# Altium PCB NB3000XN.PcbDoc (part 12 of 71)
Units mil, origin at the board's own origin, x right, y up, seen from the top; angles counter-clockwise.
Board outline 9527.56 x 6929.77 mil, 6 copper layers (Top Layer, GND+SHIELD, MidLayer1, MidLayer2, P2 - 3V3+5V0, Bottom Layer), stack 62.375 mil thick; 832 components, 1027 nets, 4655 pads, 4981 vias.
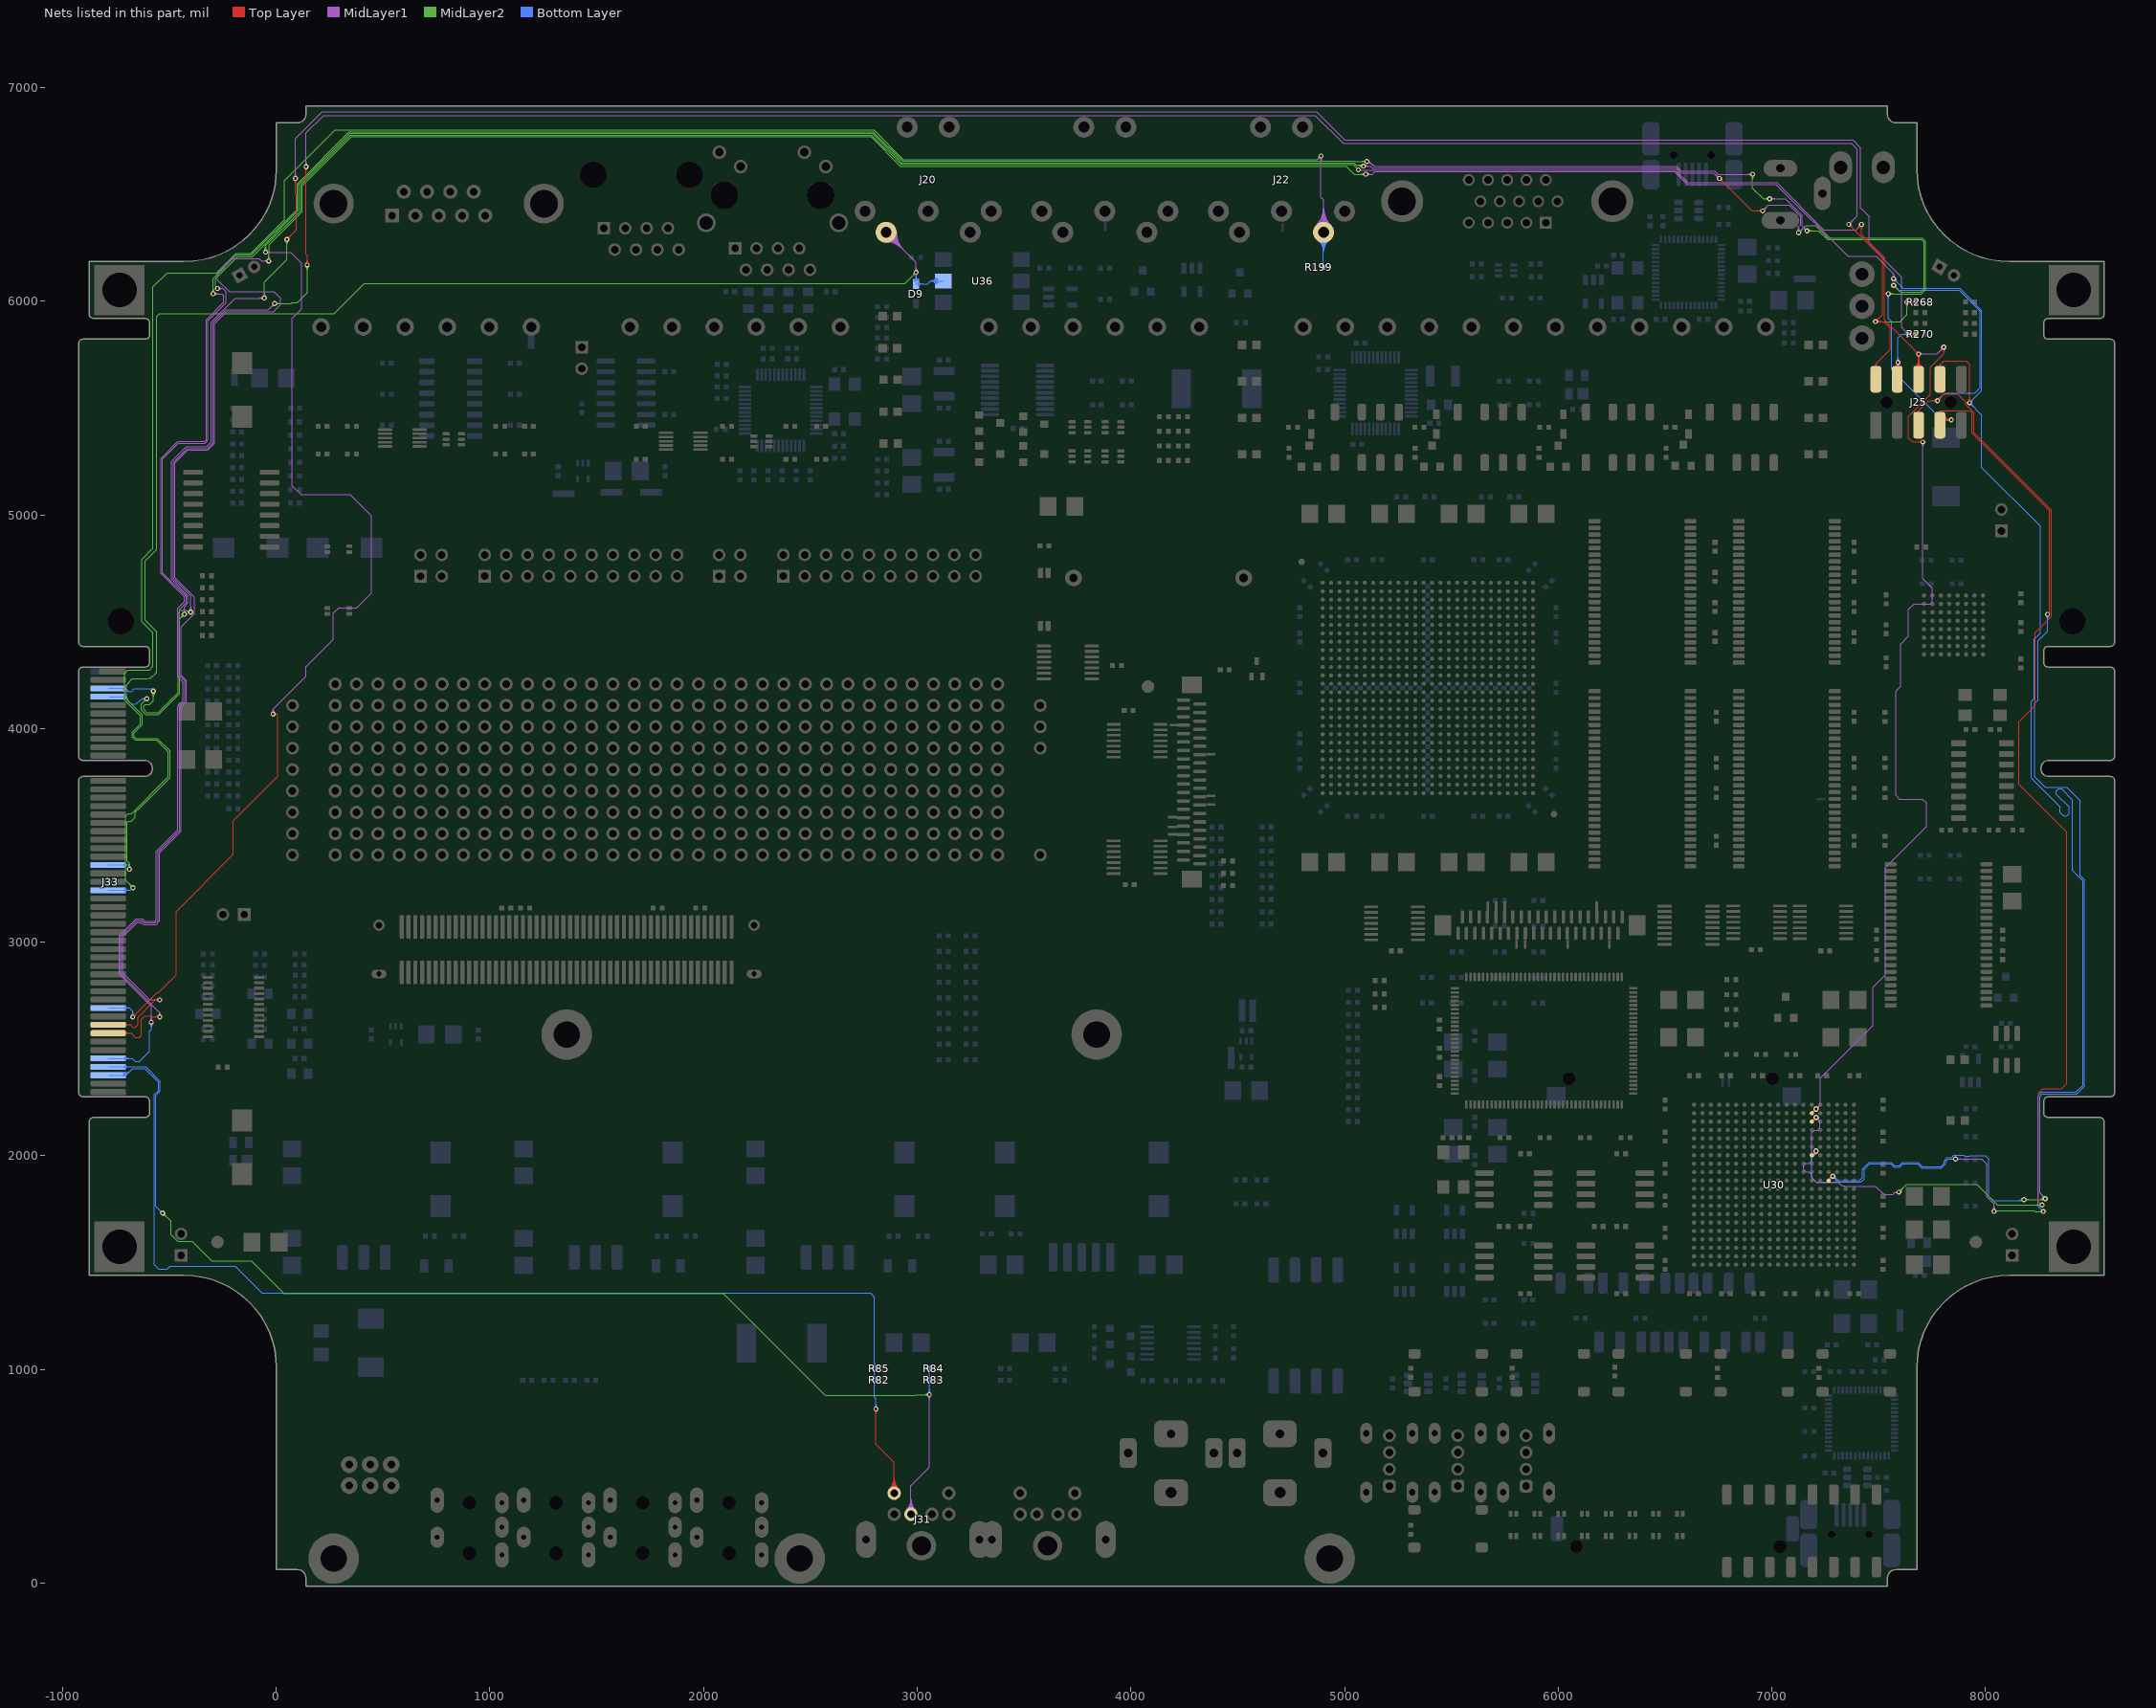
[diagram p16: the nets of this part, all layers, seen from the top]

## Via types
v1: diameter 23, hole 11.81, Top Layer to Bottom Layer, 3672 vias
v2: diameter 26, hole 11.81, Top Layer to Bottom Layer, 461 vias
v3: diameter 19, hole 11.81, Top Layer to Bottom Layer, tented both sides, 396 vias
v4: diameter 23.62, hole 11.81, Top Layer to Bottom Layer, 288 vias
v5: diameter 20, hole 11.81, Top Layer to Bottom Layer, 91 vias
v6: diameter 23, hole 11.81, Top Layer to Bottom Layer, tented both sides, 50 vias
v7: diameter 31, hole 11.81, Top Layer to Bottom Layer, 15 vias
v8: diameter 27.56, hole 11.81, Top Layer to Bottom Layer, tented both sides, 4 vias
v9: diameter 29, hole 11.81, Top Layer to Bottom Layer, 3 vias
v10: diameter 21, hole 11.81, Top Layer to Bottom Layer, 1 vias

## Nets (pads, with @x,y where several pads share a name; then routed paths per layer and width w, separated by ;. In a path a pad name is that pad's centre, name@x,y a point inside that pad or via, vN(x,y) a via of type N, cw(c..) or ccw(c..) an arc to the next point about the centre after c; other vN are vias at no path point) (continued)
ATE.HOST_JTAG.HARD.TDO: J25.2 J33.B3 R268.1 | length 13855.9
  Top Layer w4: v4@133.06,6623.06 cw(c116.31,6606.31) 140,6606.31 cw(c163.69,6606.31) v4@146.94,6623.06 ; v4@135.89,6625.89 cw(c125.97,6615.97) 140,6615.97 cw(c154.03,6615.97) v4@144.11,6625.89 ; v4@138.06,6176.94 ccw(c121.31,6193.69) 145,6193.69 ccw(c168.69,6193.69) v4@151.94,6176.94 ; v4(140,6630) 140,6220 145,6215 v4(145,6170) ; v4@140.89,6174.11 ccw(c130.97,6184.03) 145,6184.03 ccw(c159.03,6184.03) v4@149.11,6174.11 ; v4@7360,6350.19 cw(c7360,6326.5) 7376.75,6343.25 cw(c7393.5,6360) v4@7369.81,6360 ; v4@7360,6354.19 cw(c7360,6340.16) 7369.92,6350.08 cw(c7379.84,6360) v4@7365.81,6360 ; v4(7360,6360) 7518.05,6201.95 7518.05,5938.05 v4(7485,5905) 7524.05,5905 7555,5874.05 7555,5775 7486.99,5706.99 ; J25.2@7478.3,5694.04 ccw(c7473.01,5706.99) 7486.99,5706.99 ; J25.2@7479.81,5690.34 ccw(c7475.44,5701.04) 7486.99,5701.04 ccw(c7498.55,5701.04) J25.2@7494.18,5690.34 ; J25.2@7481.58,5695.1 ccw(c7479.91,5701.99) 7486.99,5701.99 ; J25.2@7484.89,5574.85 cw(c7484.68,5572.54) 7486.99,5572.54 ; v4@7485,5910.81 ccw(c7485,5924.84) 7494.92,5914.92 ccw(c7504.84,5905) v4@7490.81,5905 ; v4@7485,5914.81 ccw(c7485,5938.5) 7501.75,5921.75 ccw(c7518.5,5905) v4@7494.81,5905 ; J25.2@7489.1,5574.85 ccw(c7489.31,5572.54) 7486.99,5572.54 ; v4@7489.11,5900.89 cw(c7499.03,5890.97) 7499.03,5905 cw(c7499.03,5919.03) v4@7489.11,5909.11 ; v4@7491.94,5898.06 cw(c7508.69,5881.31) 7508.69,5905 cw(c7508.69,5928.69) v4@7491.94,5911.94 ; J25.2@7492.41,5695.1 cw(c7494.08,5701.99) 7486.99,5701.99 ; J25.2@7495.69,5694.04 cw(c7500.98,5706.99) 7486.99,5706.99 ; v4(7632,5997) R268.1@7673.82,5997 ; v4@7636.11,5992.89 cw(c7646.03,5982.97) 7646.03,5997 cw(c7646.03,6011.03) v4@7636.11,6001.11 ; v4@7638.94,5990.06 cw(c7655.69,5973.31) 7655.69,5997 cw(c7655.69,6020.69) v4@7638.94,6003.94 ; R268.1@7667.23,5990.41 ccw(c7651.32,5974.5) 7651.32,5997 ccw(c7651.32,6019.5) R268.1@7667.23,6003.59 ; R268.1@7670.06,5993.24 ccw(c7660.98,5984.16) 7660.98,5997 ccw(c7660.98,6009.84) R268.1@7670.06,6000.76 ; 7486.99,5572.54 J25.2@7486.99,5635.25 ; J25.2@7486.99,5635.25 J25.2@7486.99,5635.59 ; J25.2@7486.99,5635.25 J25.2@7486.99,5635.59 ; J25.2@7486.99,5635.59 7486.99,5706.99 ; J25.2@7486.99,5635.59 7486.99,5701.99
  MidLayer1 w4: v4@-406.94,4551.94 ccw(c-423.69,4568.69) -400,4568.69 ccw(c-376.31,4568.69) v4@-393.06,4551.94 ; v4@-404.11,4549.11 ccw(c-414.03,4559.03) -400,4559.03 ccw(c-385.97,4559.03) v4@-395.89,4549.11 ; v4(-400,4545) -400,4620 -407.83,4627.84 -482,4702 -482,5246.69 -417.12,5311.56 -322.46,5311.56 -295.52,5338.51 -295.52,5899.23 -234.74,5960 -36.47,5960 v4(-7.38,5989.09) ; v4@-17.19,5989.09 cw(c-40.87,5989.09) -24.13,5972.34 cw(c-7.38,5955.59) v4@-7.38,5979.28 ; v4@-13.19,5989.09 cw(c-27.22,5989.09) -17.3,5979.17 cw(c-7.38,5969.25) v4@-7.38,5983.28 ; v4@133.06,6636.94 ccw(c116.31,6653.69) 140,6653.69 ccw(c163.69,6653.69) v4@146.94,6636.94 ; v4@135.89,6634.11 ccw(c125.97,6644.03) 140,6644.03 ccw(c154.03,6644.03) v4@144.11,6634.11 ; v4(140,6630) 140,6788.69 221.59,6870.28 4862.1,6870.28 4993.37,6739 7372.06,6739 7400,6711.06 7400,6400 v4(7360,6360) ; v4@7360,6365.81 ccw(c7360,6379.84) 7369.92,6369.92 ccw(c7379.84,6360) v4@7365.81,6360 ; v4@7360,6369.81 ccw(c7360,6393.5) 7376.75,6376.75 ccw(c7393.5,6360) v4@7369.81,6360
  MidLayer2 w4: v4@-581.94,4168.06 cw(c-598.69,4151.31) -575,4151.31 cw(c-551.31,4151.31) v4@-568.06,4168.06 ; v4@-579.11,4170.89 cw(c-589.03,4160.97) -575,4160.97 cw(c-560.97,4160.97) v4@-570.89,4170.89 ; v4(-575,4175) -575,4131.31 -593.81,4112.5 -612.5,4112.5 -620,4105 -620,4090 -605.61,4075.61 -551.61,4075.61 -458.98,4168.24 -458.98,4541.21 -447.19,4553 -420,4553 -412,4545 v4(-400,4545) ; v4(-7.38,5989.09) 70.59,5989.09 75,5993.5 98.5,5993.5 145,6040 v4(145,6170) ; v4@-3.27,5984.98 cw(c6.65,5975.06) 6.65,5989.09 cw(c6.65,6003.12) v4@-3.27,5993.2 ; v4@-0.44,5982.15 cw(c16.31,5965.4) 16.31,5989.09 cw(c16.31,6012.77) v4@-0.44,5996.02 ; v4@138.06,6163.06 cw(c121.31,6146.31) 145,6146.31 cw(c168.69,6146.31) v4@151.94,6163.06 ; v4@140.89,6165.89 cw(c130.97,6155.97) 145,6155.97 cw(c159.03,6155.97) v4@149.11,6165.89 ; v4(7485,5905) 7600,5905 7632,5937 v4(7632,5997) ; v4@7489.11,5900.89 cw(c7499.03,5890.97) 7499.03,5905 cw(c7499.03,5919.03) v4@7489.11,5909.11 ; v4@7491.94,5898.06 cw(c7508.69,5881.31) 7508.69,5905 cw(c7508.69,5928.69) v4@7491.94,5911.94 ; v4@7625.06,5990.06 cw(c7608.31,5973.31) 7632,5973.31 cw(c7655.69,5973.31) v4@7638.94,5990.06 ; v4@7627.89,5992.89 cw(c7617.97,5982.97) 7632,5982.97 cw(c7646.03,5982.97) v4@7636.11,5992.89
  Bottom Layer w4: J33.B3@-785.98,4188.29 -705.14,4188.29 -691.06,4174.21 -676.56,4174.21 -664.89,4185.87 -580.87,4185.87 v4@-575,4180 ; J33.B3@-717.13,4188.51 cw(c-713.23,4170.99) -700.53,4183.68 ; J33.B3@-716.26,4184.61 cw(c-711.35,4162.57) -695.39,4178.53 ; J33.B3@-715.39,4180.7 cw(c-709.47,4154.15) -690.24,4173.39
ATE.HOST_JTAG.HARD.TMS: J25.4 J33.B4 R270.1 | length 13306.8
  Top Layer w4: v4(50,6290) 95,6335 95,6500 90,6505 v4(90,6575) ; v4@50,6295.81 ccw(c50,6309.84) 59.92,6299.92 ccw(c69.84,6290) v4@55.81,6290 ; v4@50,6299.81 ccw(c50,6323.5) 66.75,6306.75 ccw(c83.5,6290) v4@59.81,6290 ; v4@83.06,6568.06 cw(c66.31,6551.31) 90,6551.31 cw(c113.69,6551.31) v4@96.94,6568.06 ; v4@85.89,6570.89 cw(c75.97,6560.97) 90,6560.97 cw(c104.03,6560.97) v4@94.11,6570.89 ; J25.4@7577.2,5693.56 ccw(c7567.56,5714.04) v1(7590.19,5714.04) ; J25.4@7578.9,5689.94 ccw(c7570.52,5707.74) v1@7590.19,5707.74 ; J25.4@7580.6,5686.32 ccw(c7573.49,5701.43) 7590.19,5701.43 ; v1@7583.47,5707.32 cw(c7567.26,5691.11) 7590.19,5691.11 cw(c7613.13,5691.11) v1@7596.91,5707.32 ; J25.4@7585,5630 J25.4@7590.19,5635.19 ; v1@7586.3,5710.15 cw(c7576.91,5700.76) 7590.19,5700.76 cw(c7603.47,5700.76) v1@7594.08,5710.15 ; J25.4@7590.19,5635.25 v1(7590.19,5714.04) ; v1@7590.19,5705.7 ccw(c7613.44,5705.7) J25.4@7598.89,5687.57 ; J25.4@7601.39,5690.69 cw(c7620.13,5714.04) v1(7590.19,5714.04) ; v4(7640,5845) 7672.82,5845 R270.1@7673.82,5846 ; v4@7644.11,5840.89 cw(c7654.03,5830.97) 7654.03,5845 cw(c7654.03,5859.03) v4@7644.11,5849.11 ; v4@7646.94,5838.06 cw(c7663.69,5821.31) 7663.69,5845 cw(c7663.69,5868.69) v4@7646.94,5851.94 ; v4@7650.09,5845 ccw(c7650.09,5869.23) R270.1@7667.23,5852.1 ; 7652.55,5845 cw(c7652.55,5824.24) R270.1@7667.23,5838.92 ; 7659.75,5845 ccw(c7659.75,5859.57) R270.1@7670.06,5849.27 ; 7662.2,5845 cw(c7662.2,5833.89) R270.1@7670.06,5841.75
  MidLayer1 w4: v4@-436.94,4541.94 ccw(c-453.69,4558.69) -430,4558.69 ccw(c-406.31,4558.69) v4@-423.06,4541.94 ; v4@-434.11,4539.11 ccw(c-444.03,4549.03) -430,4549.03 ccw(c-415.97,4549.03) v4@-425.89,4539.11 ; v4(-430,4535) -430,4570.19 -413.5,4586.69 -413.5,4622.19 -490,4698.69 -490,5250 -420.44,5319.56 -325.78,5319.56 -303.52,5341.82 -303.52,5902.54 -191.06,6015 v4(-55,6015) ; v4@-61.94,6008.06 ccw(c-78.69,5991.31) -78.69,6015 ccw(c-78.69,6038.69) v4@-61.94,6021.94 ; v4@-59.11,6010.89 ccw(c-69.03,6000.97) -69.03,6015 ccw(c-69.03,6029.03) v4@-59.11,6019.11 ; v4@83.06,6581.94 ccw(c66.31,6598.69) 90,6598.69 ccw(c113.69,6598.69) v4@96.94,6581.94 ; v4@85.89,6579.11 ccw(c75.97,6589.03) 90,6589.03 ccw(c104.03,6589.03) v4@94.11,6579.11 ; v4(90,6575) 90,6761.31 214.96,6886.28 4868.72,6886.28 5000,6755 7378.69,6755 7416,6717.69 7416,6436.31 7454.85,6397.46 7454.85,6266.46 7590.26,6131.06 7608,6113.31 7608,5947 7608,5877 v4(7640,5845) ; v4@7630.19,5845 ccw(c7606.5,5845) 7623.25,5861.75 ccw(c7640,5878.5) v4@7640,5854.81 ; v4@7634.19,5845 ccw(c7620.16,5845) 7630.08,5854.92 ccw(c7640,5864.84) v4@7640,5850.81
  MidLayer2 w4: v4@-614.81,4140 cw(c-638.5,4140) -621.75,4123.25 cw(c-605,4106.5) v4@-605,4130.19 ; v4@-610.81,4140 cw(c-624.84,4140) -614.92,4130.08 cw(c-605,4120.16) v4@-605,4134.19 ; v4(-605,4140) -630,4115 -630,4085 -610,4065 -550.9,4065 -450.98,4164.93 -450.98,4514.02 v4(-430,4535) ; v4@-439.81,4535 cw(c-463.5,4535) -446.75,4518.25 cw(c-430,4501.5) v4@-430,4525.19 ; v4@-435.81,4535 cw(c-449.84,4535) -439.92,4525.08 cw(c-430,4515.16) v4@-430,4529.19 ; v4@-61.94,6021.94 ccw(c-78.69,6038.69) -55,6038.69 ccw(c-31.31,6038.69) v4@-48.06,6021.94 ; v4@-59.11,6019.11 ccw(c-69.03,6029.03) -55,6029.03 ccw(c-40.97,6029.03) v4@-50.89,6019.11 ; v4(-55,6015) -55,6090 50,6195 v4(50,6290) ; v4@43.06,6283.06 cw(c26.31,6266.31) 50,6266.31 cw(c73.69,6266.31) v4@56.94,6283.06 ; v4@45.89,6285.89 cw(c35.97,6275.97) 50,6275.97 cw(c64.03,6275.97) v4@54.11,6285.89
  Bottom Layer w4: J33.B4@-780,4148.92 -703.95,4148.92 -695,4139.98 -695,4131 -679,4115 -655,4115 -633.87,4136.13 -629.86,4136.13 -625.99,4140 ; J33.B4@-717.17,4149.13 cw(c-711.42,4135.58) -701.01,4145.99 ; J33.B4@-715.61,4145.45 cw(c-708.92,4129.69) -696.82,4141.79 ; v4@-612.53,4133.71 ccw(c-625.99,4122.46) -625.99,4140 ; v4@-612.53,4146.29 cw(c-625.99,4157.54) -625.99,4140 ; v4@-609.46,4136.27 ccw(c-617.43,4129.61) -617.43,4140 ccw(c-617.43,4150.39) v4@-609.46,4143.73 ; v4(-605,4140) -625.99,4140 ; v1@7583.47,5720.76 ccw(c7567.26,5736.98) 7590.19,5736.98 ccw(c7613.13,5736.98) v1@7596.91,5720.76 ; v1@7586.3,5717.93 ccw(c7576.91,5727.32) 7590.19,5727.32 ccw(c7603.47,5727.32) v1@7594.08,5717.93 ; v1(7590.19,5714.04) 7590.19,5827.37 7607.82,5845 v4(7640,5845) ; v4@7633.06,5838.06 ccw(c7616.31,5821.31) 7616.31,5845 ccw(c7616.31,5868.69) v4@7633.06,5851.94 ; v4@7635.89,5840.89 ccw(c7625.97,5830.97) 7625.97,5845 ccw(c7625.97,5859.03) v4@7635.89,5849.11
ATE.HOST_JTAG.SOFT.TCK: J25.7 J33.A42 U30.D10 | length 21667.9
  Top Layer w4: J33.A42@-785.98,2574.12 -679.12,2574.12 -660,2555 -640,2555 -630,2565 -630,2640 -615,2655 -585,2655 -580,2650 v4(-545,2650) ; J33.A42@-711.58,2568.62 cw(c-698.3,2555.34) -698.3,2574.12 cw(c-698.3,2592.9) J33.A42@-711.58,2579.62 ; J33.A42@-708.76,2565.79 cw(c-688.65,2545.68) -688.65,2574.12 cw(c-688.65,2602.56) J33.A42@-708.76,2582.45 ; v4@-551.94,2643.06 ccw(c-568.69,2626.31) -568.69,2650 ccw(c-568.69,2673.69) v4@-551.94,2656.94 ; v4@-549.11,2645.89 ccw(c-559.03,2635.97) -559.03,2650 ccw(c-559.03,2664.03) v4@-549.11,2654.11 ; v4@6755,6565.19 cw(c6755,6541.5) 6771.75,6558.25 cw(c6788.5,6575) v4@6764.81,6575 ; v4@6755,6569.19 cw(c6755,6555.16) 6764.92,6565.08 cw(c6774.84,6575) v4@6760.81,6575 ; v4(6755,6575) 6907,6423 v4(6957,6423) ; v4@6950.06,6416.06 ccw(c6933.31,6399.31) 6933.31,6423 ccw(c6933.31,6446.69) v4@6950.06,6429.94 ; v4@6952.89,6418.89 ccw(c6942.97,6408.97) 6942.97,6423 ccw(c6942.97,6437.03) v4@6952.89,6427.11 ; J25.7@7781.58,5480.1 ccw(c7779.91,5486.99) 7786.99,5486.99 ; J25.7@7789.78,5458.88 ccw(c7810.35,5467.19) J25.7@7810.35,5445 ; J25.7@7792.41,5480.1 cw(c7794.08,5486.99) 7786.99,5486.99 ; J25.7@7793.48,5460.37 ccw(c7816.28,5469.58) 7816.28,5445 ; J25.7@7797.19,5461.87 ccw(c7822.21,5471.98) 7822.21,5445 ; J25.7@7800.9,5463.37 ccw(c7828.14,5474.38) 7828.14,5445 ; J25.7@7803.26,5441.49 cw(c7811.73,5433.01) J25.7@7811.73,5445 ; J25.7@7804.61,5464.87 ccw(c7834.07,5476.77) v4@7834.07,5445 ; J25.7@7808.32,5466.37 ccw(c7840,5479.17) v4(7840,5445) ; v4@7833.06,5438.06 ccw(c7816.31,5421.31) 7816.31,5445 ccw(c7816.31,5468.69) v4@7833.06,5451.94 ; v4@7835.89,5440.89 ccw(c7825.97,5430.97) 7825.97,5445 ccw(c7825.97,5459.03) v4@7835.89,5449.11 ; v4(7840,5445) J25.7@7811.74,5445 ; v4(8290,4535) 8299.81,4544.81 8299.81,5018.88 7937,5381.69 7937,5476.5 7924.75,5488.75 7788.75,5488.75 7786.99,5486.99 ; 7786.99,5486.99 J25.7@7786.99,5420.25 J25.7@7811.74,5445
  Top Layer w8: U30.D10@7265.91,1884.68 v2(7285.59,1904.37) ; U30.D10@7265.91,1890.53 ccw(c7265.91,1904.63) 7275.88,1894.66 ccw(c7285.85,1884.68) U30.D10@7271.75,1884.68 ; v2@7276.59,1904.37 cw(c7254.86,1904.37) 7270.23,1889.01 cw(c7285.59,1873.64) v2@7285.59,1895.37
  MidLayer1 w4: -553,3211.14 -553,3103.31 -565.11,3091.21 -619.58,3091.21 -628.91,3100.54 -653.35,3100.54 -726.5,3027.39 -726.5,2852.79 -545,2671.29 ; -552.98,3211.16 -552.98,3422.93 -460.78,3515.13 -452.81,3523.1 -452.81,4103.31 -428,4128.12 -428,4221.88 -452.81,4246.69 -452.81,4558.69 -421.5,4590 -421.5,4618.88 -532.14,4729.52 -532.14,5261.54 -458.12,5335.56 -332.4,5335.56 -319.52,5348.45 -319.52,5909.17 -235,5993.69 -235,6045.19 -249.15,6059.34 ; v4@-551.37,2657.46 ccw(c-563.2,2671.29) -545,2671.29 ; v4@-548.78,2654.42 ccw(c-555.78,2662.61) -545,2662.61 ccw(c-534.22,2662.61) v4@-541.22,2654.42 ; v4(-545,2650) -545,2671.29 ; v4@-538.63,2657.46 cw(c-526.8,2671.29) -545,2671.29 ; v4(-275,6060) -249.15,6060 ; v4@-270.89,6055.89 cw(c-260.97,6045.97) -260.97,6060 cw(c-260.97,6074.03) v4@-270.89,6064.11 ; v4@-268.06,6053.06 cw(c-251.31,6036.31) -251.31,6060 cw(c-251.31,6083.69) v4@-268.06,6066.94 ; v4(5088.13,6632.81) 5122.19,6632.81 5132,6623 6550.25,6623 6571.69,6601.56 6728.44,6601.56 v4(6755,6575) ; v4@5092.23,6628.7 cw(c5102.15,6618.78) 5102.15,6632.81 cw(c5102.15,6646.84) v4@5092.23,6636.92 ; v4@5095.06,6625.87 cw(c5111.81,6609.13) 5111.81,6632.81 cw(c5111.81,6656.5) v4@5095.06,6639.75 ; v4@6745.19,6575 ccw(c6721.5,6575) 6738.25,6591.75 ccw(c6755,6608.5) v4@6755,6584.81 ; v4@6749.19,6575 ccw(c6735.16,6575) 6745.08,6584.92 ccw(c6755,6594.84) v4@6755,6580.81 ; v4(6957,6423) 6984,6450 7082.01,6450 7134.58,6397.42 7134.58,6359.84 7125,6350.25 v4(7125,6320) ; v4@6957,6428.81 ccw(c6957,6442.84) 6966.92,6432.92 ccw(c6976.84,6423) v4@6962.81,6423 ; v4@6957,6432.81 ccw(c6957,6456.5) 6973.75,6439.75 ccw(c6990.5,6423) v4@6966.81,6423 ; v4@7118.06,6326.94 ccw(c7101.31,6343.69) 7125,6343.69 ccw(c7148.69,6343.69) v4@7131.94,6326.94 ; v4@7120.89,6324.11 ccw(c7110.97,6334.03) 7125,6334.03 ccw(c7139.03,6334.03) v4@7129.11,6324.11
  MidLayer2 w4: v4(-275,6060) -285,6070 -285,6105 -181.05,6208.95 -112.36,6208.95 106,6427.31 106,6546.94 345.06,6786 2790.31,6786 2911.31,6665 2928.31,6648 5043.31,6648 5054.31,6637 ; 5063.98,6637 cw(c5063.98,6608.67) v4@5084.02,6628.7 ; 5073.64,6637 cw(c5073.64,6618.33) v4@5086.85,6631.53 ; 5074.55,6637 ccw(c5074.55,6646.38) v4@5081.19,6639.75 ; v4@5081.19,6625.87 ccw(c5054.33,6599.01) 5054.33,6637 ; v4(5088.13,6632.81) 5092.19,6632.81 5088,6637 5054.31,6637 ; v4(7125,6320) 7160,6355 7205,6355 7263.5,6296.5 7703.5,6296.5 7720,6280 7720,6055 7700,6035 v4(7545,6035) ; v4@7125,6325.81 ccw(c7125,6339.84) 7134.92,6329.92 ccw(c7144.84,6320) v4@7130.81,6320 ; v4@7125,6329.81 ccw(c7125,6353.5) 7141.75,6336.75 ccw(c7158.5,6320) v4@7134.81,6320 ; v4@7549.11,6030.89 cw(c7559.03,6020.97) 7559.03,6035 cw(c7559.03,6049.03) v4@7549.11,6039.11 ; v4@7551.94,6028.06 cw(c7568.69,6011.31) 7568.69,6035 cw(c7568.69,6058.69) v4@7551.94,6041.94 ; v4(8180,1795) 8275,1795 v4(8280,1800) ; v4@8184.11,1790.89 cw(c8194.03,1780.97) 8194.03,1795 cw(c8194.03,1809.03) v4@8184.11,1799.11 ; v4@8186.94,1788.06 cw(c8203.69,1771.31) 8203.69,1795 cw(c8203.69,1818.69) v4@8186.94,1801.94 ; 8244.24,1795 ccw(c8244.24,1835.76) v4@8273.06,1806.94 ; 8253.9,1795 ccw(c8253.9,1826.1) v4@8275.89,1804.11 ; 8263.56,1795 ccw(c8263.56,1816.44) v4@8278.72,1801.28 ; 8268.39,1795 cw(c8268.39,1788.39) v4@8273.06,1793.06
  Bottom Layer w4: v2@7285.59,1893.37 cw(c7285.59,1866.81) 7304.37,1885.59 cw(c7323.15,1904.37) v2@7296.59,1904.37 ; v2@7285.59,1897.37 cw(c7285.59,1880.47) 7297.54,1892.42 cw(c7309.49,1904.37) v2@7292.59,1904.37 ; v2(7285.59,1904.37) 7304.96,1885 7411.2,1885 7424.02,1897.82 7424.02,1939.21 7455.19,1970.37 7558.79,1970.37 7559.5,1969.67 7559.5,1969.44 7574.44,1954.5 7595.56,1954.5 7611.27,1970.21 7684.4,1970.21 7704.6,1950 7790.4,1950 7806.36,1965.96 7806.36,1977.27 7821.29,1992.21 7842.02,1992.21 7852.62,2002.81 7899.36,2002.81 7902.67,1999.5 7927.71,1999.5 7929.09,2000.87 7999.13,2000.87 8015.48,1984.52 8015.48,1811.35 8036.83,1790 8175,1790 v4(8180,1795) ; v4@7538.06,6028.06 cw(c7521.31,6011.31) 7545,6011.31 cw(c7568.69,6011.31) v4@7551.94,6028.06 ; v4@7540.89,6030.89 cw(c7530.97,6020.97) 7545,6020.97 cw(c7559.03,6020.97) v4@7549.11,6030.89 ; v4(7545,6035) 7545,5920 7560,5905 7560,5680 7795,5445 v4(7840,5445) ; v4@7833.06,5438.06 ccw(c7816.31,5421.31) 7816.31,5445 ccw(c7816.31,5468.69) v4@7833.06,5451.94 ; v4@7835.89,5440.89 ccw(c7825.97,5430.97) 7825.97,5445 ccw(c7825.97,5459.03) v4@7835.89,5449.11 ; 8144.24,1790 ccw(c8144.24,1830.76) v4@8173.06,1801.94 ; 8153.9,1790 ccw(c8153.9,1821.1) v4@8175.89,1799.11 ; 8163.56,1790 ccw(c8163.56,1811.44) v4@8178.72,1796.28 ; 8168.39,1790 cw(c8168.39,1783.39) v4@8173.06,1788.06 ; v4@8270.19,1800 ccw(c8246.5,1800) 8263.25,1816.75 ccw(c8280,1833.5) v4@8280,1809.81 ; v4@8274.19,1800 ccw(c8260.16,1800) 8270.08,1809.92 ccw(c8280,1819.84) v4@8280,1805.81 ; v4(8280,1800) 8254,1826 8254,2276.93 8267.01,2289.94 8427.31,2289.94 8464,2326.62 8464,3289.94 8442.5,3311.44 8442.5,3662.5 8379.46,3725.54 8337.96,3725.54 8336.97,3724.55 8280.45,3724.55 8231.36,3773.64 8231.36,4119.73 8245,4133.37 8245,4410 8290,4455 v4(8290,4535) ; v4@8283.06,4528.06 cw(c8266.31,4511.31) 8290,4511.31 cw(c8313.69,4511.31) v4@8296.94,4528.06 ; v4@8285.89,4530.89 cw(c8275.97,4520.97) 8290,4520.97 cw(c8304.03,4520.97) v4@8294.11,4530.89
ATE.HOST_JTAG.SOFT.TDI: J25.5 J33.B45 U30.F3 | length 22022.3
  Top Layer w4: J25.5@7681.58,5480.1 ccw(c7679.91,5486.99) 7686.99,5486.99 ; J25.5@7686.99,5420.25 7686.99,5486.99 ; J25.5@7692.41,5480.1 cw(c7694.08,5486.99) 7686.99,5486.99 ; v4@7768.06,5528.06 ccw(c7751.31,5511.31) 7751.31,5535 ccw(c7751.31,5558.69) v4@7768.06,5541.94 ; v4@7770.89,5530.89 ccw(c7760.97,5520.97) 7760.97,5535 ccw(c7760.97,5549.03) v4@7770.89,5539.11 ; v4@7775,5540.81 ccw(c7775,5554.84) 7784.92,5544.92 ccw(c7794.84,5535) v4@7780.81,5535 ; v4@7775,5544.81 ccw(c7775,5568.5) 7791.75,5551.75 ccw(c7808.5,5535) v4@7784.81,5535 ; 8248.03,1980.89 8248.03,1985.86 8248.86,1986.69 8248.86,2293.86 8270,2315 8355,2315 8380,2340 8380,3515.58 8156.19,3739.39 8156.19,4031.59 8232.02,4107.43 8232.02,4449.21 8307.81,4525 8307.81,5022.19 7945,5385 7945,5479.81 7907.19,5517.62 7907.19,5527.81 7870,5565 7805,5565 v4(7775,5535) 7735,5535 7686.99,5486.99 ; 8248.19,1980.73 8248.19,1786.81 v4(8265,1770) ; v4@8255.19,1770 ccw(c8231.5,1770) 8248.25,1786.75 ccw(c8265,1803.5) v4@8265,1779.81 ; v4@8259.19,1770 ccw(c8245.16,1770) 8255.08,1779.92 ccw(c8265,1789.84) v4@8265,1775.81
  Top Layer w8: U30.F3@7187.17,2160.28 v2(7206.85,2179.96) ; U30.F3@7187.17,2166.12 ccw(c7187.17,2180.22) 7197.14,2170.25 ccw(c7207.11,2160.28) U30.F3@7193.01,2160.28 ; v2@7197.85,2179.96 cw(c7176.12,2179.96) 7191.49,2164.6 cw(c7206.85,2149.23) v2@7206.85,2170.96
  MidLayer1 w4: v1@-591.53,2631.76 ccw(c-607.74,2647.98) -584.81,2647.98 ccw(c-561.87,2647.98) v1@-578.09,2631.76 ; v1@-588.7,2628.93 ccw(c-598.09,2638.32) -584.81,2638.32 ccw(c-571.53,2638.32) v1@-580.92,2628.93 ; v1(-584.81,2625.04) -584.81,2699.79 -734.5,2849.48 -734.5,3030.71 -656.67,3108.54 -625.6,3108.54 -616.27,3099.21 -568.42,3099.21 -561,3106.63 -561,3214.45 -560.98,3426.25 -460.81,3526.41 -460.81,4106.63 -436,4131.44 -436,4218.56 -460.81,4243.37 -460.81,4562.01 -429.5,4593.32 -429.5,4615.56 -540.14,4726.21 -540.14,5264.86 -461.44,5343.56 -335.72,5343.56 -327.52,5351.76 -327.52,5912.48 -245,5995 -245,6025 -255,6035 v4(-295,6035) ; v4@-290.89,6030.89 cw(c-280.97,6020.97) -280.97,6035 cw(c-280.97,6049.03) v4@-290.89,6039.11 ; v4@-288.06,6028.06 cw(c-271.31,6011.31) -271.31,6035 cw(c-271.31,6058.69) v4@-288.06,6041.94 ; v4@5105,6645.19 cw(c5105,6597.36) 5138.82,6631.18 ; v4@5105,6649.19 cw(c5105,6611.02) 5131.99,6638.01 ; v4@5105,6653.19 cw(c5105,6624.67) 5125.16,6644.84 ; v4(5105,6655) 5115,6655 5139,6631 6553.56,6631 6575,6609.56 6732.45,6609.56 6747.01,6595 v4(6910,6595) ; v4@5105,6657.19 cw(c5105,6638.33) 5118.33,6651.67 ; v4@6903.06,6588.06 ccw(c6886.31,6571.31) 6886.31,6595 ccw(c6886.31,6618.69) v4@6903.06,6601.94 ; v4@6905.89,6590.89 ccw(c6895.97,6580.97) 6895.97,6595 ccw(c6895.97,6609.03) v4@6905.89,6599.11 ; v4(6990,6480) 7063.32,6480 7068.32,6475 7142.58,6400.74 7142.58,6352.42 v4(7165,6330) ; v4@6994.11,6475.89 cw(c7004.03,6465.97) 7004.03,6480 cw(c7004.03,6494.03) v4@6994.11,6484.11 ; v4@6996.94,6473.06 cw(c7013.69,6456.31) 7013.69,6480 cw(c7013.69,6503.69) v4@6996.94,6486.94 ; v4@7155.19,6330 ccw(c7131.5,6330) 7148.25,6346.75 ccw(c7165,6363.5) v4@7165,6339.81 ; v4@7159.19,6330 ccw(c7145.16,6330) 7155.08,6339.92 ccw(c7165,6349.84) v4@7165,6335.81 ; v2@7206.85,2168.96 cw(c7206.85,2142.4) 7225.63,2161.18 cw(c7244.41,2179.96) v2@7217.85,2179.96 ; v2@7206.85,2172.96 cw(c7206.85,2156.06) 7218.8,2168.01 cw(c7230.75,2179.96) v2@7213.85,2179.96 ; v2(7206.85,2179.96) 7225.86,2160.95 7225.86,2131.04 7215.19,2120.37 7199.13,2120.37 7186.52,2107.76 7186.52,1975.28 7175.35,1964.11 7160.98,1964.11 7148.48,1951.61 7148.48,1935.87 7159.61,1924.74 7173.98,1924.74 7186.48,1912.24 7186.48,1897.87 7209.15,1875.2 7312.66,1875.2 7327.23,1860.63 7339.46,1860.63 7341.88,1858.21 7485.73,1858.21 7524.44,1819.5 7567,1819.5 7575,1827.5 ; 7577.35,1827.5 cw(c7577.35,1812.35) v4@7588.06,1823.06 ; 7581.5,1827.5 ccw(c7581.5,1836.81) v4@7589.81,1832.62 ; v4@7586.24,1834.42 cw(c7575,1840.09) 7575,1827.5 ; v4@7592.5,1827.5 7575,1827.5
  MidLayer2 w4: v4@-301.94,6041.94 ccw(c-318.69,6058.69) -295,6058.69 ccw(c-271.31,6058.69) v4@-288.06,6041.94 ; v4@-299.11,6039.11 ccw(c-309.03,6049.03) -295,6049.03 ccw(c-280.97,6049.03) v4@-290.89,6039.11 ; v4(-295,6035) -295,6106.31 -184.36,6216.95 -115.68,6216.95 98,6430.63 98,6550.26 341.74,6794 2793.63,6794 2931.63,6656 5046.63,6656 5047.63,6655 v4(5105,6655) ; v4@5098.06,6648.06 ccw(c5081.31,6631.31) 5081.31,6655 ccw(c5081.31,6678.69) v4@5098.06,6661.94 ; v4@5100.89,6650.89 ccw(c5090.97,6640.97) 5090.97,6655 ccw(c5090.97,6669.03) v4@5100.89,6659.11 ; v4@6903.06,6588.06 cw(c6886.31,6571.31) 6910,6571.31 cw(c6933.69,6571.31) v4@6916.94,6588.06 ; v4@6905.89,6590.89 cw(c6895.97,6580.97) 6910,6580.97 cw(c6924.03,6580.97) v4@6914.11,6590.89 ; v4(6910,6595) 6910,6530 6960,6480 v4(6990,6480) ; v4@6983.06,6473.06 ccw(c6966.31,6456.31) 6966.31,6480 ccw(c6966.31,6503.69) v4@6983.06,6486.94 ; v4@6985.89,6475.89 ccw(c6975.97,6465.97) 6975.97,6480 ccw(c6975.97,6494.03) v4@6985.89,6484.11 ; v4(7165,6330) 7218.69,6330 7260.19,6288.5 7700.19,6288.5 7712,6276.69 7712,6058.31 7696.69,6043 7602,6043 v4(7570,6075) ; v4@7169.11,6325.89 cw(c7179.03,6315.97) 7179.03,6330 cw(c7179.03,6344.03) v4@7169.11,6334.11 ; v4@7171.94,6323.06 cw(c7188.69,6306.31) 7188.69,6330 cw(c7188.69,6353.69) v4@7171.94,6336.94 ; v4@7570,6065.19 cw(c7570,6041.5) 7586.75,6058.25 cw(c7603.5,6075) v4@7579.81,6075 ; v4@7570,6069.19 cw(c7570,6055.16) 7579.92,6065.08 cw(c7589.84,6075) v4@7575.81,6075 ; v4(7595,1830) 7630.87,1865.87 7959.13,1865.87 8055,1770 v4(8265,1770) ; v4@7595,1835.81 ccw(c7595,1849.84) 7604.92,1839.92 ccw(c7614.84,1830) v4@7600.81,1830 ; v4@7595,1839.81 ccw(c7595,1863.5) 7611.75,1846.75 ccw(c7628.5,1830) v4@7604.81,1830 ; v4@8258.06,1763.06 ccw(c8241.31,1746.31) 8241.31,1770 ccw(c8241.31,1793.69) v4@8258.06,1776.94 ; v4@8260.89,1765.89 ccw(c8250.97,1755.97) 8250.97,1770 ccw(c8250.97,1784.03) v4@8260.89,1774.11
  Bottom Layer w4: J33.B45@-785.98,2456.01 -673.84,2456.01 -659.54,2441.71 -640.48,2441.71 -593.14,2489.04 -593.14,2583.37 -584.81,2591.71 v1(-584.81,2625.04) ; J33.B45@-711.58,2450.51 cw(c-698.3,2437.23) -698.3,2456.01 cw(c-698.3,2474.79) J33.B45@-711.58,2461.51 ; J33.B45@-708.76,2447.68 cw(c-688.65,2427.57) -688.65,2456.01 cw(c-688.65,2484.45) J33.B45@-708.76,2464.34 ; v1@-591.53,2618.32 cw(c-607.74,2602.11) -584.81,2602.11 cw(c-561.87,2602.11) v1@-578.09,2618.32 ; v1@-588.7,2621.15 cw(c-598.09,2611.76) -584.81,2611.76 cw(c-571.53,2611.76) v1@-580.92,2621.15 ; v4@7570,6065.19 cw(c7570,6041.5) 7586.75,6058.25 cw(c7603.5,6075) v4@7579.81,6075 ; v4@7570,6069.19 cw(c7570,6055.16) 7579.92,6065.08 cw(c7589.84,6075) v4@7575.81,6075 ; v4(7570,6075) 7593,6052 7876.33,6052 7974.81,5953.52 7974.81,5595 7949.81,5570 7810,5570 v4(7775,5535) ; v4@7775,5540.81 ccw(c7775,5554.84) 7784.92,5544.92 ccw(c7794.84,5535) v4@7780.81,5535 ; v4@7775,5544.81 ccw(c7775,5568.5) 7791.75,5551.75 ccw(c7808.5,5535) v4@7784.81,5535
ATE.HOST_JTAG.SOFT.TDO: J25.6 J33.B39 U30.F2 | length 19230.6
  Top Layer w4: v1(-671.81,2650.04) -556.69,2765.16 -550.02,2765.16 -468.14,2847.04 -468.14,3144.08 -201.35,3410.87 -201.35,3568.4 6.86,3776.6 6.86,4063.14 2.29,4067.71 ; v1@-671.81,2655.54 ccw(c-671.81,2668.82) -662.42,2659.43 ccw(c-653.03,2650.04) v1@-666.31,2650.04 ; v1@-671.81,2659.54 ccw(c-671.81,2682.48) -655.59,2666.26 ccw(c-639.37,2650.04) v1@-662.31,2650.04 ; v1(-14.48,4067.71) 2.29,4067.71 ; v1@-6.33,4062.82 cw(c2.29,4057.66) 2.29,4067.71 ; v1@-6.33,4072.59 ccw(c2.29,4077.75) 2.29,4067.71 ; v4@7413.06,6353.06 cw(c7396.31,6336.31) 7420,6336.31 cw(c7443.69,6336.31) v4@7426.94,6353.06 ; v4@7415.89,6355.89 cw(c7405.97,6345.97) 7420,6345.97 cw(c7434.03,6345.97) v4@7424.11,6355.89 ; v4(7420,6360) 7420,6311.31 7526.05,6205.27 7526.05,5914.32 7559.25,5881.12 v4(7686.99,5753.37) J25.6@7686.99,5635.25 ; J25.6@7670.73,5689.02 ccw(c7631.46,5728.28) 7686.99,5728.28 ccw(c7742.52,5728.28) J25.6@7703.26,5689.02 ; J25.6@7673.56,5686.19 ccw(c7641.12,5718.62) 7686.99,5718.62 ccw(c7732.86,5718.62) J25.6@7700.43,5686.19 ; J25.6@7676.39,5683.36 ccw(c7650.78,5708.97) 7686.99,5708.97 ccw(c7723.2,5708.96) J25.6@7697.6,5683.36 ; v4@7677.18,5753.37 ccw(c7653.5,5753.37) 7670.25,5770.12 ccw(c7686.99,5786.87) v4@7686.99,5763.19 ; J25.6@7679.22,5680.53 ccw(c7660.44,5699.31) 7686.99,5699.31 ccw(c7713.55,5699.31) J25.6@7694.77,5680.53 ; v4@7680.06,5746.44 cw(c7663.31,5729.69) 7686.99,5729.69 cw(c7710.68,5729.69) v4@7693.93,5746.44 ; v4@7681.18,5753.37 ccw(c7667.15,5753.37) 7677.07,5763.29 ccw(c7686.99,5773.21) v4@7686.99,5759.19 ; v4@7682.89,5749.27 cw(c7672.97,5739.35) 7686.99,5739.35 cw(c7701.02,5739.35) v4@7691.1,5749.27 ; v1@7700.14,5334.99 ccw(c7683.92,5318.77) 7683.92,5341.71 ccw(c7683.92,5364.64) v1@7700.14,5348.43 ; v1@7702.97,5337.82 ccw(c7693.58,5328.43) 7693.58,5341.71 ccw(c7693.58,5354.99) v1@7702.97,5345.6 ; v1(7706.86,5341.71) 7658.29,5341.71 7640,5360 7640,5461.92 7742.41,5564.33 7742.41,5692.41 7805,5755 v4(7805,5785) ; v4@7798.06,5778.06 cw(c7781.31,5761.31) 7805,5761.31 cw(c7828.69,5761.31) v4@7811.94,5778.06 ; v4@7800.89,5780.89 cw(c7790.97,5770.97) 7805,5770.97 cw(c7819.03,5770.97) v4@7809.11,5780.89
  Top Layer w8: U30.F2@7187.17,2199.65 v2(7206.85,2219.33) ; U30.F2@7187.17,2205.49 ccw(c7187.17,2219.59) 7197.14,2209.62 ccw(c7207.11,2199.65) U30.F2@7193.01,2199.65 ; v2@7197.85,2219.33 cw(c7176.12,2219.33) 7191.49,2203.97 cw(c7206.85,2188.6) v2@7206.85,2210.33
  MidLayer1 w4: v4(-50,6230) 68.31,6230 120,6178.31 120,5965 75,5920 75,5136.9 116.9,5095 345,5095 445.5,4994.5 445.5,4635.5 376.04,4566.04 293.54,4566.04 267.5,4540 267.5,4417.5 140.19,4290.19 140.19,4245.44 -14.48,4090.78 v1(-14.48,4067.71) ; v4@-45.89,6225.89 cw(c-35.97,6215.97) -35.97,6230 cw(c-35.97,6244.03) v4@-45.89,6234.11 ; v4@-43.06,6223.06 cw(c-26.31,6206.31) -26.31,6230 cw(c-26.31,6253.69) v4@-43.06,6236.94 ; v1@-21.19,4074.43 ccw(c-37.41,4090.64) -14.48,4090.64 ccw(c8.46,4090.64) v1@-7.76,4074.43 ; v1@-18.36,4071.6 ccw(c-27.75,4080.99) -14.48,4080.99 ccw(c-1.2,4080.99) v1@-10.59,4071.6 ; v4(5065,6615) 6546.93,6615 6606.93,6555 7022.26,6555 7242.26,6335 7395,6335 v4(7420,6360) ; v2(7206.85,2219.33) 7227.19,2239.67 7227.19,2363.04 7473.52,2609.37 7473.52,2788.73 7530,2845.2 7531.86,2847.06 7531.86,3350.04 7723.52,3541.71 7723.52,3651.22 7705.1,3669.65 7596.92,3669.65 7580.29,3686.28 7580.29,4174.49 7602.52,4196.73 7602.52,4395.71 7640.19,4433.37 7640.19,4558.37 7665.19,4583.37 7743.19,4583.37 7751.52,4591.71 7751.52,4657.04 7706.86,4701.71 v1(7706.86,5341.71) ; v2@7206.85,2226.33 ccw(c7206.85,2243.23) 7218.8,2231.28 ccw(c7230.75,2219.33) v2@7213.85,2219.33 ; v2@7206.85,2230.33 ccw(c7206.85,2256.89) 7225.63,2238.11 ccw(c7244.41,2219.33) v2@7217.85,2219.33 ; v4@7410.19,6360 cw(c7386.5,6360) 7403.25,6343.25 cw(c7420,6326.5) v4@7420,6350.19 ; v4@7414.19,6360 cw(c7400.16,6360) 7410.08,6350.08 cw(c7420,6340.16) v4@7420,6354.19 ; v4(7686.99,5753.37) 7773.37,5753.37 v4(7805,5785) ; v4@7691.1,5749.27 cw(c7701.02,5739.35) 7701.02,5753.37 cw(c7701.02,5767.4) v4@7691.1,5757.48 ; v4@7693.93,5746.44 cw(c7710.68,5729.69) 7710.68,5753.37 cw(c7710.68,5777.06) v4@7693.93,5760.31 ; v1@7700.14,5334.99 cw(c7683.92,5318.77) 7706.86,5318.77 cw(c7729.79,5318.77) v1@7713.57,5334.99 ; v1@7702.97,5337.82 cw(c7693.58,5328.43) 7706.86,5328.43 cw(c7720.14,5328.43) v1@7710.75,5337.82 ; v4@7795.19,5785 cw(c7771.5,5785) 7788.25,5768.25 cw(c7805,5751.5) v4@7805,5775.19 ; v4@7799.19,5785 cw(c7785.16,5785) 7795.08,5775.08 cw(c7805,5765.16) v4@7805,5779.19
  MidLayer2 w4: v4@-56.94,6236.94 ccw(c-73.69,6253.69) -50,6253.69 ccw(c-26.31,6253.69) v4@-43.06,6236.94 ; v4@-54.11,6234.11 ccw(c-64.03,6244.03) -50,6244.03 ccw(c-35.97,6244.03) v4@-45.89,6234.11 ; v4(-50,6230) -50,6260 114,6424 114,6543.63 348.37,6778 2787,6778 2925,6640 5040,6640 v4(5065,6615)
  Bottom Layer w4: J33.B39@-711.58,2686.73 cw(c-698.3,2673.45) -698.3,2692.23 cw(c-698.3,2711.01) J33.B39@-711.58,2697.73 ; J33.B39@-708.76,2683.9 cw(c-688.65,2663.79) -688.65,2692.23 cw(c-688.65,2720.67) J33.B39@-708.76,2700.56 ; -703,2692.23 J33.B39@-785.98,2692.23 -687.23,2692.23 -671.81,2676.81 v1(-671.81,2650.04) ; v1@-678.53,2656.76 ccw(c-694.74,2672.98) -671.81,2672.98 ccw(c-648.87,2672.98) v1@-665.09,2656.76 ; v1@-675.7,2653.93 ccw(c-685.09,2663.32) -671.81,2663.32 ccw(c-658.53,2663.32) v1@-667.92,2653.93 ; v2@7206.85,2216.71 v2(7206.85,2219.33)
ATE.HOST_JTAG.SOFT.TMS: J25.8 J33.A41 U30.F7 | length 21682.1
  Top Layer w4: J33.A41@-785.98,2613.49 -682.24,2613.49 -669.29,2600.54 -660.71,2600.54 -647.5,2613.75 -647.5,2647.5 -565,2730 ; J33.A41@-711.58,2607.99 cw(c-698.3,2594.71) -698.3,2613.49 cw(c-698.3,2632.27) J33.A41@-711.58,2618.99 ; J33.A41@-708.76,2605.16 cw(c-688.65,2585.05) -688.65,2613.49 cw(c-688.65,2641.93) J33.A41@-708.76,2621.82 ; v4@-552.76,2724 ccw(c-565,2714.52) -565,2730 ; v4@-552.76,2736 cw(c-565,2745.48) -565,2730 ; v4@-549.6,2726.44 ccw(c-556.85,2720.83) -556.85,2730 ccw(c-556.85,2739.17) v4@-549.6,2733.56 ; v4(-545,2730) -565,2730 ; J25.8@7781.58,5695.1 ccw(c7779.91,5701.99) 7786.99,5701.99 ; J25.8@7786.99,5635.25 7786.99,5701.99 ; J25.8@7792.41,5695.1 cw(c7794.08,5701.99) 7786.99,5701.99 ; v4@7918.06,5531.94 ccw(c7901.31,5548.69) 7925,5548.69 ccw(c7948.69,5548.69) v4@7931.94,5531.94 ; v4@7920.89,5529.11 ccw(c7910.97,5539.03) 7925,5539.03 ccw(c7939.03,5539.03) v4@7929.11,5529.11 ; v4(7925,5525) 7925,5705 7910,5720 7805,5720 7786.99,5701.99
  Top Layer w8: U30.F7@7187.17,2002.8 v2(7206.85,2022.48) ; U30.F7@7187.17,2008.64 ccw(c7187.17,2022.74) 7197.14,2012.77 ccw(c7207.11,2002.8) U30.F7@7193.01,2002.8 ; v2@7197.85,2022.48 cw(c7176.12,2022.48) 7191.49,2007.12 cw(c7206.85,1991.75) v2@7206.85,2013.48
  MidLayer1 w4: v4@-551.94,2723.06 ccw(c-568.69,2706.31) -568.69,2730 ccw(c-568.69,2753.69) v4@-551.94,2736.94 ; v4@-549.11,2725.89 ccw(c-559.03,2715.97) -559.03,2730 ccw(c-559.03,2744.03) v4@-549.11,2734.11 ; v4(-545,2730) -592.39,2730 -718.5,2856.11 -718.5,3024.08 -650.04,3092.54 -632.23,3092.54 -622.89,3083.21 -561.79,3083.21 -545,3100 -545,3207.83 ; -544.98,3207.85 -544.98,3419.62 -444.81,3519.79 -444.81,4100 -420,4124.81 -420,4225.19 -444.81,4250 -444.81,4475 -382.19,4537.62 -382.19,4613.51 -474,4705.32 -474,5243.37 -413.81,5303.56 -319.15,5303.56 -287.52,5335.19 -287.52,5895.92 -231.43,5952 -13,5952 20,5985 20,6015 -10,6045 -220,6045 -275,6100 -275,6133.69 -207.73,6200.95 -80.95,6200.95 -67.95,6187.95 v4(-35,6187.95) ; v4@-41.94,6181.01 ccw(c-58.69,6164.27) -58.69,6187.95 ccw(c-58.69,6211.64) v4@-41.94,6194.89 ; v4@-39.11,6183.84 ccw(c-49.03,6173.92) -49.03,6187.95 ccw(c-49.03,6201.98) v4@-39.11,6192.06 ; v4(5100,6595) 5130,6595 5142,6607 6543.62,6607 6603.62,6547 7018.95,6547 7355.95,6210 7488.69,6210 7570,6128.69 ; v4@5104.11,6590.89 cw(c5114.03,6580.97) 5114.03,6595 cw(c5114.03,6609.03) v4@5104.11,6599.11 ; v4@5106.94,6588.06 cw(c5123.69,6571.31) 5123.69,6595 cw(c5123.69,6618.69) v4@5106.94,6601.94 ; v4@7563.06,6111.94 ccw(c7546.31,6128.69) 7570,6128.69 ; v4@7565.89,6109.11 ccw(c7555.97,6119.03) 7570,6119.03 ccw(c7584.03,6119.03) v4@7574.11,6109.11 ; v4(7570,6105) 7570,6128.69 ; v4@7576.94,6111.94 cw(c7593.69,6128.69) 7570,6128.69 ; v4(7860,1985) 7982.48,1985 8007.48,1960 8007.48,1808.03 8040,1775.51 v4(8040,1740) ; v4@7864.11,1980.89 cw(c7874.03,1970.97) 7874.03,1985 cw(c7874.03,1999.03) v4@7864.11,1989.11 ; v4@7866.94,1978.06 cw(c7883.69,1961.31) 7883.69,1985 cw(c7883.69,2008.69) v4@7866.94,1991.94 ; v4@8033.06,1746.94 ccw(c8016.31,1763.69) 8040,1763.69 ccw(c8063.69,1763.69) v4@8046.94,1746.94 ; v4@8035.89,1744.11 ccw(c8025.97,1754.03) 8040,1754.03 ccw(c8054.03,1754.03) v4@8044.11,1744.11
  MidLayer2 w4: v4@-41.94,6194.89 ccw(c-58.69,6211.64) -35,6211.64 ccw(c-11.31,6211.64) v4@-28.06,6194.89 ; v4@-39.11,6192.06 ccw(c-49.03,6201.98) -35,6201.98 ccw(c-20.97,6201.98) v4@-30.89,6192.06 ; v4(-35,6187.95) -35,6217.19 -32.19,6220 -32.19,6265.18 122,6419.37 122,6540.31 351.69,6770 2783.69,6770 2921.69,6632 5008,6632 5045,6595 v4(5100,6595) ; v4@5093.06,6588.06 ccw(c5076.31,6571.31) 5076.31,6595 ccw(c5076.31,6618.69) v4@5093.06,6601.94 ; v4@5095.89,6590.89 ccw(c5085.97,6580.97) 5085.97,6595 ccw(c5085.97,6609.03) v4@5095.89,6599.11 ; v4(8040,1740) 8042.54,1742.54 8230,1742.54 8232.94,1739.6 v4(8270.21,1739.6)
  Bottom Layer w4: 7194.1,1997.23 ccw(c7182,2009.33) v2@7197.13,2017.34 ; 7197.93,2001.06 ccw(c7187.01,2011.98) v2@7200.66,2019.21 ; 7201.76,2004.89 ccw(c7192.02,2014.63) v2@7204.2,2021.08 ; 7205.59,2008.72 ccw(c7197.03,2017.29) v2@7207.73,2022.95 ; v2(7206.85,2022.48) 7206.85,2009.98 7187.85,1990.98 7187.85,1896.5 7207.35,1877 7417,1877 7432.02,1892.02 7432.02,1935.9 7458.5,1962.37 7555.25,1962.37 7571.12,1946.5 7598.88,1946.5 7614.58,1962.21 7681.08,1962.21 7701.29,1942 7793.71,1942 7814.36,1962.64 7814.36,1973.96 7824.61,1984.21 v4@7859.21,1984.21 ; v4@7570,6095.19 cw(c7570,6071.5) 7586.75,6088.25 cw(c7603.5,6105) v4@7579.81,6105 ; v4@7570,6099.19 cw(c7570,6085.16) 7579.92,6095.08 cw(c7589.84,6105) v4@7575.81,6105 ; v4(7570,6105) 7615,6060 7879.65,6060 7982.81,5956.84 7982.81,5582.81 v4(7925,5525) 7982.81,5467.19 7982.81,5221.11 8256.69,4947.23 8256.69,4446.69 8229,4419 8229,4140 8215.36,4126.36 8215.36,3767.01 8349.84,3632.53 8349.84,3607.31 8366.28,3590.87 8380.77,3590.87 8391.02,3601.13 8391.02,3632.79 8331.02,3692.79 8331.02,3707.29 8341.28,3717.54 8355.77,3717.54 8407.35,3665.96 8407.35,3335.27 8456,3286.63 8456,2329.94 8424,2297.94 8263.69,2297.94 8246,2280.24 8246,1763.81 v4(8270.21,1739.6) ; v4@7925,5515.19 cw(c7925,5491.5) 7941.75,5508.25 cw(c7958.5,5525) 7934.81,5525 cw(c7958.5,5525) 7941.75,5541.75 cw(c7925,5558.5) v4@7925,5534.81 ; v4@7925,5519.19 cw(c7925,5505.16) 7934.92,5515.08 cw(c7944.84,5525) 7930.81,5525 cw(c7944.84,5525) 7934.92,5534.92 cw(c7925,5544.84) v4@7925,5530.81
ATE.KBD#.CLOCK: J31.5 J33.B47 R82.2 R85.2 | length 6454.6
  Top Layer w4: v1@2800.14,808.32 cw(c2783.92,792.11) 2806.86,792.11 cw(c2829.79,792.11) v1@2813.57,808.32 ; v1@2802.97,811.15 cw(c2793.58,801.76) 2806.86,801.76 cw(c2820.14,801.76) v1@2810.75,811.15 ; v1(2806.86,815.04) 2806.86,650.04 2892.05,564.85 J31.5@2892.05,421.1 ; J31.5@2871.19,441.96 ccw(c2820.84,492.31) 2892.05,492.31 ccw(c2963.26,492.31) J31.5@2912.9,441.96 ; J31.5@2874.02,439.13 ccw(c2830.49,482.66) 2892.05,482.66 ccw(c2953.6,482.66) J31.5@2910.08,439.13 ; J31.5@2876.85,436.3 ccw(c2840.15,473) 2892.05,473 ccw(c2943.94,473) J31.5@2907.25,436.3 ; J31.5@2879.68,433.47 ccw(c2849.81,463.34) 2892.05,463.34 ccw(c2934.29,463.34) J31.5@2904.42,433.47 ; J31.5@2882.5,430.65 ccw(c2859.47,453.68) 2892.05,453.68 ccw(c2924.63,453.68) J31.5@2901.59,430.65
  Bottom Layer w4: J33.B47@-785.98,2377.27 -702.73,2377.27 -671.36,2408.64 -614.95,2408.64 -551,2344.69 -551,2306.63 -571,2286.63 -571,1489.52 -551.48,1470 -510,1470 -496.29,1483.71 -191.1,1483.71 -66.44,1359.04 2780.96,1359.04 2800.87,1339.13 R85.2@2800.87,1005 R82.2@2800.87,950 2800.87,869.13 2806.86,863.14 v1(2806.86,815.04) ; J33.B47@-717.08,2373.05 ccw(c-717.08,2397.52) -699.78,2380.22 ; J33.B47@-717.08,2377.05 ccw(c-717.08,2411.17) -692.96,2387.04 ; J33.B47@-717.08,2381.05 ccw(c-717.08,2424.83) -686.13,2393.87 ; J33.B47@-717.08,2385.05 ccw(c-717.08,2438.49) -679.3,2400.7 ; J33.B47@-717.08,2389.05 ccw(c-717.08,2452.14) -672.47,2407.53 ; R82.2@2794.28,942.92 cw(c2778.37,927.01) 2800.87,927.01 cw(c2823.36,927.01) R82.2@2807.46,942.92 ; R82.2@2794.28,957.08 ccw(c2778.37,972.99) 2800.87,972.99 ccw(c2823.36,972.99) R82.2@2807.46,957.08 ; R85.2@2794.28,997.92 cw(c2778.37,982.01) 2800.87,982.01 cw(c2823.36,982.01) R85.2@2807.46,997.92 ; R85.2@2794.28,1012.08 ccw(c2778.37,1027.99) 2800.87,1027.99 ccw(c2823.36,1027.99) R85.2@2807.46,1012.08 ; R82.2@2797.11,945.75 cw(c2788.02,936.67) 2800.87,936.67 cw(c2813.71,936.67) R82.2@2804.63,945.75 ; R82.2@2797.11,954.25 ccw(c2788.02,963.33) 2800.87,963.33 ccw(c2813.71,963.33) R82.2@2804.63,954.25 ; R85.2@2797.11,1000.75 cw(c2788.02,991.67) 2800.87,991.67 cw(c2813.71,991.67) R85.2@2804.63,1000.75 ; R85.2@2797.11,1009.25 ccw(c2788.02,1018.33) 2800.87,1018.33 ccw(c2813.71,1018.33) R85.2@2804.63,1009.25 ; v1@2800.14,821.76 ccw(c2783.92,837.98) 2806.86,837.98 ccw(c2829.79,837.98) v1@2813.57,821.76 ; v1@2802.97,818.93 ccw(c2793.58,828.32) 2806.86,828.32 ccw(c2820.14,828.32) v1@2810.75,818.93
ATE.KBD#.DATA: J31.1 J33.B46 R83.2 R84.2 | length 6538.2
  MidLayer1 w4: J31.1@2949.93,343.53 ccw(c2899.58,393.89) 2970.79,393.89 ccw(c3042,393.89) J31.1@2991.64,343.53 ; J31.1@2952.76,340.71 ccw(c2909.23,384.23) 2970.79,384.23 ccw(c3032.34,384.23) J31.1@2988.82,340.71 ; J31.1@2955.59,337.88 ccw(c2918.89,374.57) 2970.79,374.57 ccw(c3022.68,374.57) J31.1@2985.99,337.88 ; J31.1@2958.42,335.05 ccw(c2928.55,364.92) 2970.79,364.92 ccw(c3013.03,364.92) J31.1@2983.16,335.05 ; J31.1@2961.24,332.22 ccw(c2938.21,355.26) 2970.79,355.26 ccw(c3003.37,355.26) J31.1@2980.33,332.22 ; J31.1@2970.79,322.68 2970.79,456.3 2981.52,467.04 3056.86,542.37 v1(3056.86,882.37) ; v1@3050.14,875.66 cw(c3033.92,859.44) 3056.86,859.44 cw(c3079.79,859.44) v1@3063.57,875.66 ; v1@3052.97,878.49 cw(c3043.58,869.1) 3056.86,869.1 cw(c3070.14,869.1) v1@3060.75,878.49
  MidLayer2 w4: v1@-531.81,1722.54 cw(c-531.81,1699.61) -515.59,1715.82 cw(c-499.37,1732.04) v1@-522.31,1732.04 ; v1@-531.81,1726.54 cw(c-531.81,1713.26) -522.42,1722.65 cw(c-513.03,1732.04) v1@-526.31,1732.04 ; v1(-531.81,1732.04) -493.14,1693.37 -493.14,1632.23 -460.01,1599.09 -392.73,1599.09 -301.13,1507.5 -114.87,1507.5 36.63,1356 2092.56,1356 2542.42,906.14 2569.57,879 2989,879 2992.37,882.37 v1(3056.86,882.37) ; v1@3050.14,875.66 ccw(c3033.92,859.44) 3033.92,882.37 ccw(c3033.92,905.31) v1@3050.14,889.09 ; v1@3052.97,878.49 ccw(c3043.58,869.1) 3043.58,882.37 ccw(c3043.58,895.65) v1@3052.97,886.26
  Bottom Layer w4: J33.B46@-785.98,2416.64 -611.64,2416.64 -543,2348 -543,2303.31 -563,2283.31 -563,1763.23 v1(-531.81,1732.04) ; J33.B46@-711.58,2411.14 cw(c-698.3,2397.86) -698.3,2416.64 cw(c-698.3,2435.42) J33.B46@-711.58,2422.14 ; J33.B46@-708.76,2408.31 cw(c-688.65,2388.2) -688.65,2416.64 cw(c-688.65,2445.08) J33.B46@-708.76,2424.97 ; v1@-541.31,1732.04 ccw(c-564.24,1732.04) -548.03,1748.26 ccw(c-531.81,1764.48) v1@-531.81,1741.54 ; v1@-537.31,1732.04 ccw(c-550.59,1732.04) -541.2,1741.43 ccw(c-531.81,1750.82) v1@-531.81,1737.54 ; v1@3050.14,889.09 ccw(c3034.13,905.1) 3056.77,905.1 ; R83.2@3050.18,942.92 cw(c3034.27,927.01) 3056.77,927.01 cw(c3079.27,927.01) R83.2@3063.36,942.92 ; R83.2@3050.18,957.08 ccw(c3034.27,972.99) 3056.77,972.99 ccw(c3079.27,972.99) R83.2@3063.36,957.08 ; R84.2@3050.18,997.92 cw(c3034.27,982.01) 3056.77,982.01 cw(c3079.27,982.01) R84.2@3063.36,997.92 ; v1@3052.97,886.26 ccw(c3043.78,895.45) 3056.77,895.45 ; R83.2@3053.01,945.75 cw(c3043.93,936.67) 3056.77,936.67 cw(c3069.61,936.67) R83.2@3060.53,945.75 ; R83.2@3053.01,954.25 ccw(c3043.93,963.33) 3056.77,963.33 ccw(c3069.61,963.33) R83.2@3060.53,954.25 ; R84.2@3053.01,1000.75 cw(c3043.93,991.67) 3056.77,991.67 cw(c3069.61,991.67) R84.2@3060.53,1000.75 ; v1@3056.77,882.62 R83.2@3056.77,950 R84.2@3056.77,1005 ; 3056.77,895.86 ccw(c3070.34,895.86) v1@3060.75,886.26 ; 3056.77,905.51 ccw(c3080,905.51) v1@3063.57,889.09
ATE.MIDI#.MIDI_OUT_PWR: J22.4 J33.B25 R199.2 | length 11619.7
  MidLayer1 w4: J22.4@4868.47,6356.32 ccw(c4787.87,6436.92) 4901.85,6436.92 ccw(c5015.83,6436.92) J22.4@4935.23,6356.32 ; J22.4@4871.29,6353.49 ccw(c4797.53,6427.26) 4901.85,6427.26 ccw(c5006.17,6427.26) J22.4@4932.41,6353.49 ; J22.4@4874.12,6350.66 ccw(c4807.18,6417.6) 4901.85,6417.6 ccw(c4996.52,6417.6) J22.4@4929.58,6350.66 ; J22.4@4876.95,6347.84 ccw(c4816.84,6407.95) 4901.85,6407.95 ccw(c4986.86,6407.95) J22.4@4926.75,6347.84 ; J22.4@4879.78,6345.01 ccw(c4826.5,6398.29) 4901.85,6398.29 ccw(c4977.2,6398.29) J22.4@4923.92,6345.01 ; J22.4@4882.61,6342.18 ccw(c4836.15,6388.63) 4901.85,6388.63 ccw(c4967.55,6388.63) J22.4@4921.09,6342.18 ; v4@4883.06,6673.06 cw(c4866.31,6656.31) 4890,6656.31 cw(c4913.69,6656.31) v4@4896.94,6673.06 ; J22.4@4885.44,6339.35 ccw(c4845.81,6378.98) 4901.85,6378.98 ccw(c4957.89,6378.98) J22.4@4918.26,6339.35 ; v4@4885.89,6675.89 cw(c4875.97,6665.97) 4890,6665.97 cw(c4904.03,6665.97) v4@4894.11,6675.89 ; v4(4890,6680) 4890,6486.85 4901.85,6475 J22.4@4901.85,6322.94
  MidLayer2 w4: v1@-679.64,3255.04 ccw(c-702.58,3255.04) -686.36,3271.26 ccw(c-670.14,3287.48) v1@-670.14,3264.54 ; v1@-675.64,3255.04 ccw(c-688.92,3255.04) -679.53,3264.43 ccw(c-670.14,3273.82) v1@-670.14,3260.54 ; v1(-670.14,3255.04) -705.5,3290.4 -705.5,3589.69 -692.38,3602.81 -676.65,3602.81 -505,3774.46 -505,3890 -561.54,3946.54 -659.04,3946.54 -673.98,3961.48 -673.98,3982.6 -635.42,4021.16 -635.42,4059.11 -709.81,4133.5 -709.81,4258.37 -693.14,4275.04 -593.14,4275.04 -576.48,4291.71 -576.48,4448.08 -628.81,4500.41 -628.81,4791.63 -576.48,4843.96 -576.48,6066.71 -509.81,6133.37 -279.25,6133.37 -187.59,6225.04 -118.9,6225.04 38.39,6382.33 38.39,6564.89 275.5,6802 2796.94,6802 2934.94,6664 4874,6664 ; v4@4880.19,6679.68 cw(c4859.02,6678.98) 4874,6664 ; v4@4884.19,6679.81 cw(c4871.65,6679.4) 4880.52,6670.52 cw(c4889.4,6661.65) v4@4889.81,6674.19 ; v4@4889.68,6670.19 ccw(c4888.98,6649.02) 4874,6664 ; v4(4890,6680) 4874,6664
  Bottom Layer w4: J33.B25@-785.98,3243.41 -681.77,3243.41 v1(-670.14,3255.04) ; J33.B25@-711.58,3237.91 cw(c-698.3,3224.63) -698.3,3243.41 cw(c-698.3,3262.19) J33.B25@-711.58,3248.91 ; J33.B25@-708.76,3235.08 cw(c-688.65,3214.98) -688.65,3243.41 cw(c-688.65,3271.85) J33.B25@-708.76,3251.74 ; J22.4@4875.66,6283.65 cw(c4843.03,6234.72) 4901.85,6234.72 ; J22.4@4877.88,6286.98 cw(c4848.02,6242.19) 4901.85,6242.19 cw(c4955.68,6242.19) J22.4@4925.82,6286.98 ; J22.4@4880.1,6290.31 cw(c4853,6249.66) 4901.85,6249.66 cw(c4950.7,6249.67) J22.4@4923.6,6290.31 ; J22.4@4882.32,6293.64 cw(c4857.98,6257.14) 4901.85,6257.14 cw(c4945.72,6257.14) J22.4@4921.38,6293.64 ; J22.4@4884.54,6296.97 cw(c4862.97,6264.61) 4901.85,6264.61 cw(c4940.73,6264.61) J22.4@4919.16,6296.97 ; J22.4@4886.75,6300.3 cw(c4867.95,6272.09) 4901.85,6272.09 cw(c4935.75,6272.09) J22.4@4916.95,6300.3 ; R199.2@4894.59,6167.08 ccw(c4878.68,6182.99) 4901.18,6182.99 ccw(c4923.68,6182.99) R199.2@4907.77,6167.08 ; R199.2@4897.42,6164.25 ccw(c4888.34,6173.33) 4901.18,6173.33 ccw(c4914.02,6173.33) R199.2@4904.94,6164.25 ; R199.2@4901.18,6160 4901.18,6234.04 4901.85,6234.71 ; J22.4@4901.85,6322.94 4901.85,6234.71 ; J22.4@4928.04,6283.65 ccw(c4960.67,6234.72) 4901.85,6234.72
ATE.MIDI#.MIDI_RX_N: D9.1 J20.5 J33.B22 U36.2 | length 8790.9
  MidLayer1 w4: J20.5@2854.61,6275.72 cw(c2854.61,6161.74) 2935.2,6242.34 cw(c3015.8,6322.94) J20.5@2901.82,6322.94 ; J20.5@2854.61,6279.72 cw(c2854.61,6175.4) 2928.37,6249.17 cw(c3002.14,6322.94) J20.5@2897.82,6322.94 ; J20.5@2854.61,6283.72 cw(c2854.61,6189.06) 2921.55,6256 cw(c2988.49,6322.94) J20.5@2893.82,6322.94 ; J20.5@2854.61,6287.72 cw(c2854.61,6202.71) 2914.72,6262.83 cw(c2974.83,6322.94) J20.5@2889.82,6322.94 ; J20.5@2854.61,6291.72 cw(c2854.61,6216.37) 2907.89,6269.65 cw(c2961.17,6322.94) J20.5@2885.82,6322.94 ; J20.5@2854.61,6295.72 cw(c2854.61,6230.03) 2901.06,6276.48 cw(c2947.52,6322.94) J20.5@2881.82,6322.94 ; J20.5@2854.61,6299.72 cw(c2854.61,6243.69) 2894.23,6283.31 cw(c2933.86,6322.94) J20.5@2877.82,6322.94 ; J20.5@2854.61,6322.94 2995.19,6182.35 v1(2995.19,6135.37) ; v1@2988.47,6142.09 ccw(c2972.26,6158.31) 2995.19,6158.31 ccw(c3018.13,6158.31) v1@3001.91,6142.09 ; v1@2991.3,6139.26 ccw(c2981.91,6148.65) 2995.19,6148.65 ccw(c3008.47,6148.65) v1@2999.08,6139.26
  MidLayer2 w4: -701.48,4205 -701.48,4136.48 -627.42,4062.42 -627.42,4017.84 -665.98,3979.29 -665.98,3964.79 -655.72,3954.54 -556.54,3954.54 -497,3895 -497,3771.14 -591.44,3676.71 -636.41,3631.73 -660,3608.14 -660,3584.81 -677.62,3567.19 -692.66,3567.19 -697.5,3562.35 -697.5,3380 -687,3369.5 v1(-687,3341) ; -701.35,4205 -673.81,4232.54 -603.46,4232.54 -600.19,4235.81 -587.73,4235.81 -559.81,4263.73 -559.81,4454.04 -612.81,4507.04 -612.81,4785 -559.81,4838 -559.81,5870 ; v1@-693.72,3347.72 ccw(c-709.94,3363.93) -687,3363.93 ccw(c-664.07,3363.93) v1@-680.28,3347.72 ; v1@-690.89,3344.89 ccw(c-700.28,3354.28) -687,3354.28 ccw(c-673.72,3354.28) v1@-683.11,3344.89 ; -560,5870 -560,5930 -546.66,5943.34 81.91,5943.34 82.75,5942.5 271.44,5942.5 411.98,6083.04 2942.86,6083.04 2959.86,6100.04 v1(2995.19,6135.37) ; v1@2985.69,6135.37 cw(c2962.76,6135.37) 2978.97,6119.16 cw(c2995.19,6102.94) v1@2995.19,6125.87 ; v1@2989.69,6135.37 cw(c2976.41,6135.37) 2985.8,6125.99 cw(c2995.19,6116.6) v1@2995.19,6129.87
  Bottom Layer w4: J33.B22@-785.98,3361.52 -690,3361.52 ; J33.B22@-711.39,3356.22 cw(c-699.2,3344.85) -699.2,3361.52 cw(c-699.2,3378.19) J33.B22@-711.39,3366.83 ; J33.B22@-708.47,3353.49 cw(c-690,3336.28) -690,3361.52 ; J33.B22@-708.47,3369.55 ccw(c-690,3386.76) -690,3361.52 ; v1@-692.18,3348.96 ccw(c-698.41,3358.52) -687,3358.52 ; v1(-687,3341) -687,3358.52 ; v1@-681.82,3348.96 cw(c-675.59,3358.52) -687,3358.52 ; D9.1@2986.02,6098.16 ccw(c2965.9,6119.18) 2995,6119.18 ; D9.1@2988.78,6095.26 ccw(c2974.86,6109.82) 2995,6109.82 ccw(c3015.15,6109.82) D9.1@3001.22,6095.26 ; v1@2990.64,6127.03 cw(c2986.47,6119.38) 2995.19,6119.38 ; v1(2995.19,6135.37) 2995.19,6119.37 ; v1@2999.74,6127.03 ccw(c3003.91,6119.38) 2995.19,6119.38 ; D9.1@3001.36,6074.9 cw(c3016.73,6059.53) 3016.73,6081.26 cw(c3016.73,6102.99) D9.1@3001.36,6087.62 ; D9.1@3003.99,6098.15 cw(c3024.1,6119.18) 2995,6119.18 ; D9.1@3004.19,6072.07 cw(c3026.38,6049.88) 3026.38,6081.26 cw(c3026.39,6112.65) D9.1@3004.19,6090.45 ; U36.2@3088.47,6079.35 ccw(c3062.27,6065.24) 3062.27,6095 ; U36.2@3088.46,6110.65 cw(c3062.27,6124.76) 3062.27,6095 ; U36.2@3091.99,6081.25 ccw(c3068.96,6068.85) 3068.96,6095 ccw(c3068.96,6121.15) U36.2@3091.99,6108.75 ; U36.2@3095.51,6083.15 ccw(c3075.66,6072.46) 3075.66,6095 ccw(c3075.66,6117.54) U36.2@3095.51,6106.85 ; U36.2@3099.03,6085.04 ccw(c3082.36,6076.06) 3082.36,6095 ccw(c3082.36,6113.94) U36.2@3099.03,6104.96 ; U36.2@3122.52,6095 3062.26,6095 ; -690,3361.52 -687,3358.52 ; 2995,6119.18 D9.1@2995,6081.26 3048.52,6081.26 3062.26,6095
